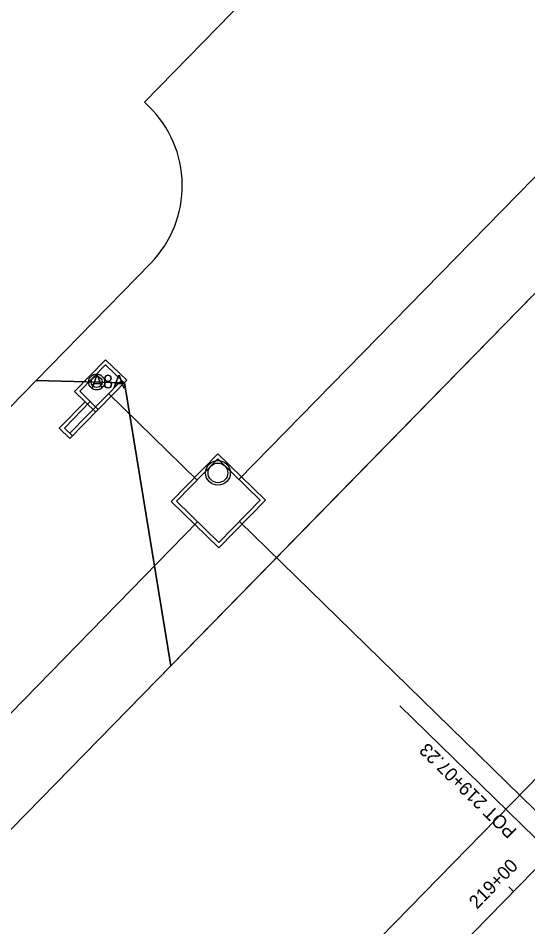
# Model space of a CAD drawing. Extents: x 2251012 to 2259557, y 13786786 to 13792525.
# Drawn here: x 2253964.2 to 2254033.1, y 13789792.3 to 13789915.2 of the extents above; entities that cross this region are included whole.
import ezdxf

# ---------------------------------------------------------------- set-up
doc = ezdxf.new("R2010")
doc.units = 0
for name, color, linetype in [('D_ALIGN_ANNO_1', 7, 'Continuous'), ('D_BOXES_1', 7, 'Continuous'), ('D_DRAIN_MISC', 7, 'Continuous'), ('D_DRAIN_NOTES_1', 7, 'Continuous'), ('D_DRN_AREA_A', 7, 'Continuous'), ('D_DRN_AREA_X', 7, 'Continuous'), ('D_INLET_1', 7, 'Continuous'), ('D_PIPES_1', 7, 'Continuous'), ('Grade_DitchLine', 7, 'Continuous')]:
    doc.layers.add(name, color=color, linetype=linetype)

msp = doc.modelspace()

# ---------------------------------------------------------------- linework, layer by layer
at = {"layer": 'D_ALIGN_ANNO_1'}
for p, q in [((2254036.03, 13789802.44), (2254015.83, 13789822.18)), ((2254031.2, 13789797.06), (2254030.55, 13789797.69))]:
    msp.add_line(p, q, dxfattribs=at)
at = {"layer": 'D_BOXES_1'}
for p, q in [((2253994.07, 13789852.79), (2254044.39, 13789904.28)), ((2253812.35, 13789666.84), (2253988.48, 13789847.07))]:
    msp.add_line(p, q, dxfattribs=at)
at = {"layer": 'D_DRAIN_MISC'}
for p, q in [((2253977.11, 13789867.27), (2253977.11, 13789867.27)), ((2253974.29, 13789866.53), (2253974.29, 13789866.53)), ((2253975.36, 13789865.48), (2253975.36, 13789865.48)), ((2253973.62, 13789863.69), (2253973.62, 13789863.69)), ((2253976.44, 13789864.43), (2253976.44, 13789864.43)), ((2253988.41, 13789852.72), (2253988.41, 13789852.72)), ((2253994.07, 13789852.79), (2253994.07, 13789852.79)), ((2253991.28, 13789849.93), (2253991.28, 13789849.93)), ((2253988.48, 13789847.07), (2253988.48, 13789847.07)), ((2253994.14, 13789847.13), (2253994.14, 13789847.13))]:
    msp.add_line(p, q, dxfattribs=at)
at = {"layer": 'D_DRN_AREA_A'}
for p, q in [((2254023.17, 13789946.84), (2253981.29, 13789903.85)), ((2253981.29, 13789903.85), (2253981.86, 13789903.32)), ((2253982.14, 13789882.07), (2253966.65, 13789866.22)), ((2253966.65, 13789866.22), (2253819.83, 13789715.98))]:
    msp.add_line(p, q, dxfattribs=at)
msp.add_arc((2253971.41, 13789892.56), 15, 315.6588, 45.8716, dxfattribs=at)
at = {"layer": 'D_DRN_AREA_X'}
for p, q in [((2254023.17, 13789946.84), (2253981.29, 13789903.85)), ((2253981.29, 13789903.85), (2253981.86, 13789903.32)), ((2254041.1, 13789885.17), (2253838.11, 13789677.46)), ((2253982.14, 13789882.07), (2253966.65, 13789866.22)), ((2254005.47, 13789848.72), (2254025.79, 13789869.5)), ((2253966.65, 13789866.22), (2253819.83, 13789715.98)), ((2253978.57, 13789865.87), (2253966.65, 13789866.22)), ((2253966.65, 13789866.22), (2253978.57, 13789865.87)), ((2253984.84, 13789827.6), (2253978.57, 13789865.87)), ((2253978.57, 13789865.87), (2253984.84, 13789827.6)), ((2253988.38, 13789831.22), (2254005.47, 13789848.72)), ((2253984.84, 13789827.6), (2253988.38, 13789831.22)), ((2253838.11, 13789677.46), (2253984.84, 13789827.6))]:
    msp.add_line(p, q, dxfattribs=at)
for points in [[(2254025.79, 13789869.5), (2254099.77, 13789945.21), (2254108.02, 13789953.74)], [(2254054.56, 13789833.13), (2253869.39, 13789643.66), (2253869.28, 13789643.54), (2253869.28, 13789643.54)], [(2253869.29, 13789643.54), (2253869.39, 13789643.65), (2254054.56, 13789833.13)]]:
    msp.add_lwpolyline(points, dxfattribs=at)
msp.add_arc((2253971.41, 13789892.56), 15, 315.6588, 45.8716, dxfattribs=at)
at = {"layer": 'D_INLET_1'}
for p, q in [((2253971.84, 13789864.73), (2253976.03, 13789869.02)), ((2253976.03, 13789869.02), (2253978.89, 13789866.23)), ((2253972.54, 13789864.74), (2253976.04, 13789868.31)), ((2253976.04, 13789868.31), (2253978.54, 13789865.87)), ((2253971.19, 13789859.07), (2253978.18, 13789866.22)), ((2253971.2, 13789858.36), (2253978.89, 13789866.23)), ((2253971.84, 13789864.73), (2253973.27, 13789863.33)), ((2253972.54, 13789864.74), (2253975.05, 13789862.29)), ((2253969.77, 13789859.76), (2253973.27, 13789863.33)), ((2253970.48, 13789859.76), (2253973.97, 13789863.34)), ((2253973.27, 13789863.33), (2253974.7, 13789861.93)), ((2253969.77, 13789859.76), (2253971.2, 13789858.36)), ((2253970.48, 13789859.76), (2253971.55, 13789858.72)), ((2253984.91, 13789849.85), (2253991.2, 13789856.29)), ((2253991.2, 13789856.29), (2253997.64, 13789850)), ((2253985.62, 13789849.86), (2253991.21, 13789855.58)), ((2253991.21, 13789855.58), (2253996.93, 13789849.99)), ((2253996.93, 13789849.99), (2253991.34, 13789844.27)), ((2253997.64, 13789850), (2253991.35, 13789843.56)), ((2253991.35, 13789843.56), (2253984.91, 13789849.85)), ((2253991.34, 13789844.27), (2253985.62, 13789849.86))]:
    msp.add_line(p, q, dxfattribs=at)
for centre, radius in [((2253974.83, 13789866), 1.08), ((2253974.83, 13789866), 0.75), ((2253991.23, 13789853.7), 1.67), ((2253991.23, 13789853.7), 1.33)]:
    msp.add_circle(centre, radius, dxfattribs=at)
at = {"layer": 'D_PIPES_1'}
for p, q in [((2253976.44, 13789864.43), (2253988.41, 13789852.72)), ((2254036.69, 13789805.54), (2253994.14, 13789847.13))]:
    msp.add_line(p, q, dxfattribs=at)
at = {"layer": 'Grade_DitchLine'}
msp.add_line((2253520.29, 13789274.27), (2254036.25, 13789802.23), dxfattribs=at)

# ---------------------------------------------------------------- texts
at = {"layer": 'D_ALIGN_ANNO_1'}
for s, rotation, p in [('POT 219+07.23', 135.6588, (2254031.76, 13789805.36)), ('219+00', 45.6588, (2254026.27, 13789794.59))]:
    msp.add_text(s, height=1.8, rotation=rotation, dxfattribs=at).set_placement(p)
at = {"layer": 'D_DRAIN_NOTES_1'}
msp.add_text('A8A', height=1.8, dxfattribs=at).set_placement((2253974.09, 13789865.15))

doc.saveas('drawing.dxf')
